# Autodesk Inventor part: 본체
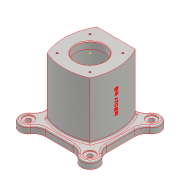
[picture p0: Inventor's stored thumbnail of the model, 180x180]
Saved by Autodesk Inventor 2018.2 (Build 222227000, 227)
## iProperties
Created: 2022-01
Part Number: 본체
Material: 알루미늄 6061
Document SubType Name: Modeling
Designer: woori
Density: 2.7 g/cm^3
Appearance: 알루미늄 - 평지
Mass: 1218.58 g
Surface Area: 907.545 cm^2
Volume: 451.327 cm^3
Author: woori
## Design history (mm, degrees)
sketch "스케치1"
  geometry: L1 (-37.928, -53)-(37.928, -53); L2 (53, -37.928)-(53, 37.928); L3 (37.928, 53)-(-37.928, 53); L4 (-53, 37.928)-(-53, -37.928); L5 (-53, -53)-(53, 53); L6 (53, -53)-(-53, 53); L7 (-90.138, 0)-(80.521, 0); L8 (0, -80.48)-(0, 80.48); L9 (0, 0)-(-73.489, 73.489); L10 (-74.306, 95.519)-(0.334, 20.879); L11 (-93.365, 72.152)-(-29.688, 8.475); C1 r 75 at (0, 0); A1 r 15.072 centre (-53, 53) between (-37.928, 53) and (-53, 37.928); A2 r 15.072 centre (-53, -53) between (-53, -37.928) and (-37.928, -53); A3 r 15.072 centre (53, -53) between (37.928, -53) and (53, -37.928); A4 r 15.072 centre (53, 53) between (53, 37.928) and (37.928, 53); 2 further points
  constraints: 22 end point, 8 point on circle, 5 centre point, 5 midpoint, 4 parallel, 2 coincident, 2 horizontal, 1 perpendicular, 1 point on line, 1 vertical, 17 other
  dimensions: "d0" = 150 diameter of C1; "d1" = 106 distance of L6.end L5.end; "d2" = 106 distance of L5.end L6.start; "d3" = 45 deg angle of L9 L8; "d4" = 15 distance between parallel lines of L9 L10; "d5" = 15 distance between parallel lines of L9 L11; "d8" = 360 deg dimension on point (0, 0) A1.centre (derived)
extrude "돌출1" new body sketch "스케치1" distance "d10" = 12; taper "d11" = 0 deg
fillet "모깎기1" dims "d12" = 20
sketch "스케치2"
  geometry: L1 (-45, -45)-(45, -45); L2 (45, -45)-(45, 45); L3 (45, 45)-(-45, 45); L4 (-45, 45)-(-45, -45); L5 (-45, -45)-(45, 45); L6 (45, -45)-(-45, 45); L7 (0, 0)-(-45, -45); L8 (-80.785, 0)-(117.597, 0); L9 (0, 53.234)-(0, -83.62); 2 further points
  constraints: 18 end point, 4 midpoint, 2 horizontal, 2 parallel, 2 point on line, 1 perpendicular, 1 vertical
  dimensions: "d16" = 90 distance of L3.end L2.end; "d17" = 90 distance of L2.end L1.end
extrude "돌출2" join sketch "스케치2" distance "d23" = 98; taper "d24" = 0 deg
sketch "스케치3" dims "d25" = 80
  geometry: L1 (-90.924, 0)-(82.794, 0); L2 (0, 150.184)-(0, -88.998); L3 (0, 0)-(-73.138, 73.138); 2 further points
  constraints: 6 end point, 3 point on line, 1 coincident, 1 horizontal, 1 vertical, 3 other
  dimensions: "d26" = 45 deg angle of L2 L3
hole "구멍1" sketch "스케치3" at (-28.284, 28.284) diameter "d27" = 3.242; stored, may be unused: countersink angle "d31" = 90 deg, drill point angle "d33" = 118 deg; dims "d28" = 9, "d29" = 4, "d30" = 2, "d32" = 11
sketch "스케치4"
  geometry: L1 (53, 24.19)-(53, -24.19) reference; L2 (53, 0)-(-53, 0); L3 (-53, -24.19)-(-53, 24.19) reference; L4 (-24.19, 53)-(24.19, 53) reference; L5 (0, 53)-(0, -73.29); L6 (0, 0)-(78.867, 78.867); C1 r 75 at (0, 0); A1 r 15.072 centre (53, 53) between (61.595, 40.619) and (40.619, 61.595) reference; 2 further points
  constraints: 6 end point, 3 midpoint, 2 coincident, 1 centre point, 1 vertical
  dimensions: "d111" = 150 diameter of C1; "d112" = 45 deg angle of L6 L5
hole "구멍2" sketch "스케치4" diameter "d37" = 9; stored, may be unused: countersink angle "d41" = 90 deg, drill point angle "d43" = 0 deg; dims "d38" = 9, "d39" = 18, "d40" = 2, "d42" = 14
sketch "스케치5"
  geometry: L1 (0, 189.335)-(0, -189.335); L2 (45, 110)-(-45, 110) reference; L3 (25, 110)-(25, 98); L4 (25, 98)-(37, 98); L5 (37, 98)-(37, 12); L6 (37, 12)-(25, 12); L7 (25, 12)-(25, 0); L8 (25, 110)-(0, 110); L9 (-24.19, 0)-(24.19, 0) reference; L10 (24.19, 0)-(40.619, 0) reference; L11 (24.19, 0)-(0, 0); L12 (0, 0)-(0, 110)
  constraints: 18 end point, 3 vertical, 2 collinear, 2 perpendicular, 1 horizontal, 1 midpoint, 1 point on line
  dimensions: "d47" = 50 diameter of L7 L1; "d48" = 12 distance from line of L7.end L6; "d49" = 86 distance of L4.end L5.end; "d50" = 74 diameter of L5 L1; "d51" = 50 diameter of L3 L1
revolve "회전1" sketch "스케치5" stored, may be unused: angle "d52" = 90 deg
node "작업 평면1"
sketch "스케치6"
  geometry: L1 (0, 0)-(0, 225.68); L2 (24.19, 0)-(-24.19, 0) reference; C1 r 20 at (0, 61)
  constraints: 2 end point, 1 centre point, 1 point on line, 1 vertical
  dimensions: "d54" = 61 distance from line of L2 C1.centre; "d55" = 40 diameter of C1
extrude "돌출3" join sketch "스케치6" stored distance "d56" = 98; taper "d57" = 0 deg
feature "면 기울기1" dims angle "d58" = 10 deg
sketch "스케치7"
  geometry: C1 r 18.237 at (0, 0) reference; C2 r 12 at (0, 0); 1 further point
  constraints: 1 centre point, 1 coincident
  dimensions: "d59" = 24 diameter of C2
extrude "돌출4" cut sketch "스케치7" distance "d60" = 13; taper "d61" = 0 deg
sketch "스케치8"
  geometry: C1 r 12 at (0, 0) reference; C2 r 15 at (0, 0); 1 further point
  constraints: 1 centre point, 1 coincident
  dimensions: "d62" = 30 diameter of C2
extrude "돌출5" cut sketch "스케치8" distance "d63" = 13; taper "d64" = 0 deg
sketch "스케치9"
  geometry: L1 (0, 135)-(0, -45); L2 (134.996, 1.209)-(-45, 0); L3 (-191.132, 0)-(101.132, 0); L4 (0, 113.574)-(0, -264.026); L5 (-45, -45)-(45, -45) reference; L6 (-45, 45)-(-45, -45) reference; L7 (-45, 0)-(-45, -45); L8 (-45, -45)-(0, -45); A1 r 90 centre (44.998, 0.604) between (-45, 0) and (-36.685, -37.184); A2 r 90 centre (0, 45) between (-36.685, -37.184) and (0, -45); 1 further point
  constraints: 12 end point, 5 midpoint, 4 point on circle, 3 point on line, 2 centre point, 2 vertical, 1 collinear, 1 horizontal
extrude "돌출6" cut sketch "스케치9" stored distance "d68" = 13; taper "d69" = 0 deg
sketch "스케치10"
  geometry: 1 further point
sketch "스케치11"
  geometry: L1 (0, 0)-(-75.181, 75.181); L2 (0, 0)-(0, 79.139); C1 r 40 at (0, 0); C2 r 1.621 at (-28.284, 28.284) reference; 2 further points
  constraints: 4 end point, 2 coincident, 1 centre point, 1 vertical
  dimensions: "d73" = 80 diameter of C1; "d74" = 45 deg angle of L1 L2
hole "구멍3" sketch "스케치11" at (-28.284, 28.284) diameter "d75" = 3.242; stored, may be unused: countersink angle "d79" = 90 deg, drill point angle "d81" = 118 deg; dims "d76" = 9, "d77" = 18, "d78" = 2, "d80" = 11
fillet "모깎기2" dims "d85" = 3
sketch "스케치12"
  geometry: L1 (0, 135)-(0, -45); L2 (-135, 0)-(45, 0); L3 (-154.364, 0)-(125.148, 0); L4 (0, 122.256)-(0, -99.92); L5 (45, -45)-(45, 45) reference; L6 (45, 45)-(-45, 45) reference; L7 (135, 0)-(-45, 0); L8 (-45, 45)-(-45, 0) reference; L9 (-32.942, 45)-(-45, 45); L10 (-45, 45)-(-45, 0); L11 (0, -45)-(45, -45); L12 (45, -45)-(45, 45); L13 (32.942, 45)-(45, 45); C1 r 90 at (54.13, 290.353); A1 r 90 centre (0, 45) between (0, -45) and (37.029, -37.029); A2 r 90 centre (-45, 0) between (37.029, -37.029) and (32.942, 45); A3 r 90 centre (44.998, 0.604) between (-45, 0) and (-36.685, -37.184) reference; A4 r 90 centre (45, 0) between (-32.942, 45) and (-45, 0); 1 further point
  constraints: 20 end point, 8 point on circle, 6 horizontal, 5 midpoint, 5 point on line, 4 centre point, 3 vertical, 1 collinear
extrude "돌출7" cut sketch "스케치12" stored distance "d87" = 13; taper "d88" = 0 deg
sketch "스케치13"
  geometry: L1 (0, -45)-(0, 135); L2 (-135, 0)-(45, 0); L3 (45, -45)-(45, 45) reference; L4 (0, -45)-(45, -45) reference; L5 (0, -45)-(45, -45); L6 (45, -45)-(45, 0); A1 r 90 centre (0, 45) between (0, -45) and (37.029, -37.029); A2 r 90 centre (45, 0) between (-32.942, 45) and (-45, 0) reference; A3 r 90 centre (-45, 0) between (37.029, -37.029) and (45, 0); 1 further point
  constraints: 8 end point, 4 point on circle, 3 midpoint, 2 centre point, 2 horizontal, 1 coincident, 1 collinear, 1 tangent, 1 vertical
  dimensions: "d90" = 180 diameter of A1
extrude "돌출8" cut sketch "스케치13" stored distance "d91" = 13; taper "d92" = 0 deg
sketch "스케치14"
  geometry: L1 (-45, 0)-(45, 0); L2 (45, 45)-(-32.942, 45) reference; L3 (32.942, 45)-(45, 45); L4 (45, 0)-(45, 45) reference; L5 (45, 45)-(45, 0); A1 r 90 centre (-45, 0) between (45, 0) and (32.942, 45); 1 further point
  constraints: 6 end point, 3 point on circle, 2 collinear, 1 centre point, 1 coincident, 1 horizontal, 1 point on line, 1 tangent
extrude "돌출9" cut sketch "스케치14" stored distance "d95" = 13; taper "d96" = 0 deg
fillet "모깎기3" dims "d97" = 3
fillet "모깎기4" dims "d98" = 3
chamfer "모따기1" distance "d99" = 1; stored, may be unused: second distance "d100" = 2, angle "d101" = 45 deg
chamfer "모따기2" distance "d102" = 1; stored, may be unused: second distance "d103" = 2, angle "d104" = 45 deg
fillet "모깎기5" dims "d105" = 3
node "작업 평면2"
sketch "스케치15"
  geometry: L1 (19.839, 86.118)-(19.839, 35.882); L2 (19.839, 35.882)-(-19.839, 35.882); L3 (-19.839, 35.882)-(-19.839, 86.118); L4 (-19.839, 86.118)-(19.839, 86.118); L5 (0, 86.118)-(0, 35.882); L6 (55, 79.237)-(55, 42.763) reference; L7 (19.839, 61)-(-19.839, 61); L8 (40.619, 0)-(68.072, 0) reference; 2 further points
  constraints: 4 end point, 4 midpoint, 2 other
  dimensions: "d107" = 55 distance between parallel lines of L6 L5; "d108" = 61 distance between parallel lines of L8 L7
extrude "돌출10" join sketch "스케치15" stored distance "d109" = 13; taper "d110" = 0 deg
node "솔리드1"
pattern_circular "원형 패턴1" dims angle "d14" = 360 deg
pattern_circular "원형 패턴2" dims angle "d35" = 360 deg
pattern_circular "원형 패턴3" dims angle "d45" = 360 deg
pattern_circular "원형 패턴5" dims angle "d83" = 360 deg
other parameters: "d53" = 55, "d106" = 45.5
